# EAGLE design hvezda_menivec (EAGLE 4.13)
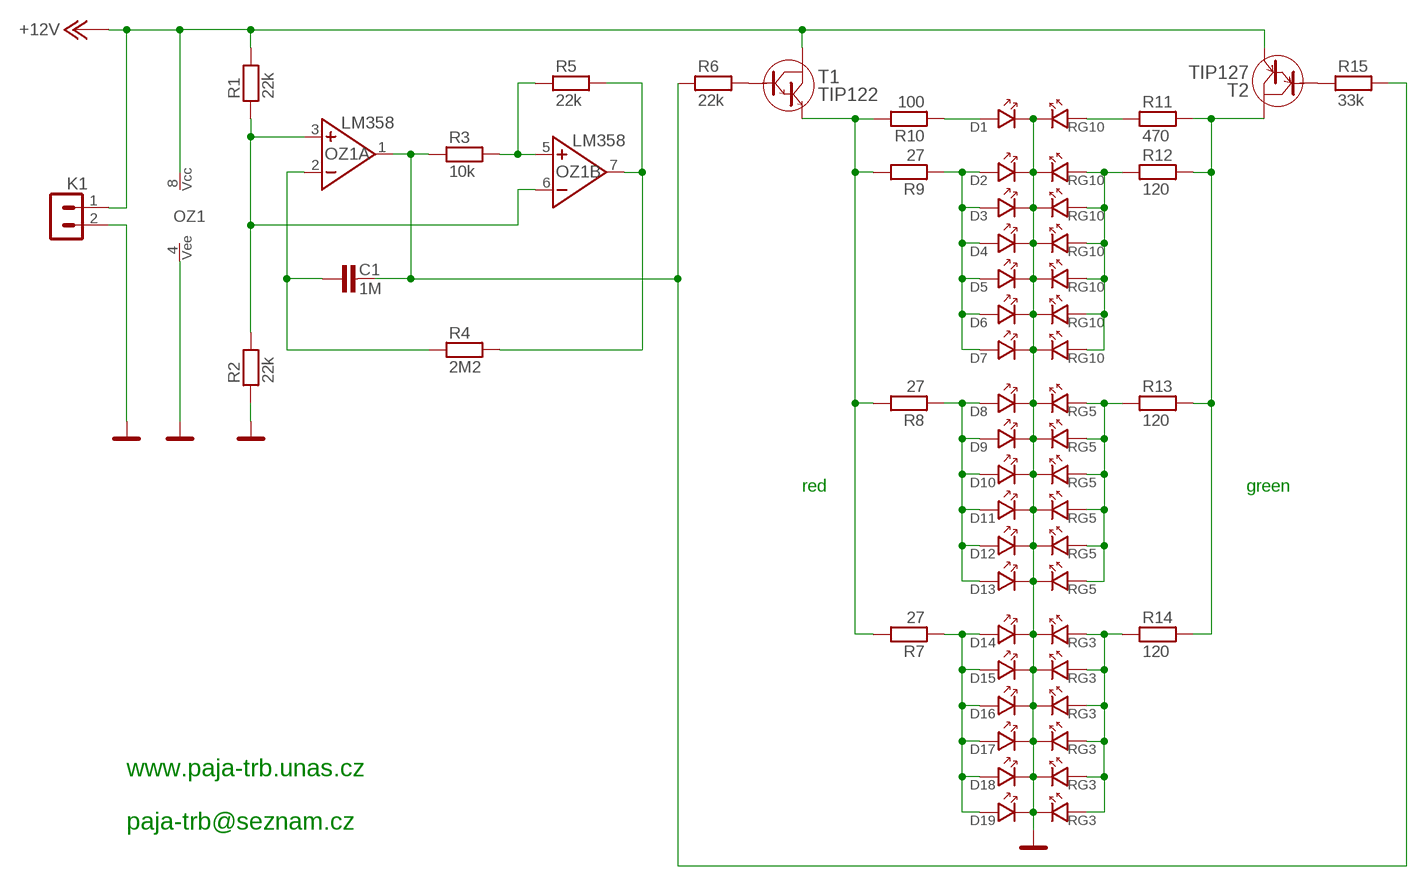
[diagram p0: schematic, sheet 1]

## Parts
C1  1M  1M-K/63V  [RM5_5,0]
D1  RG10  LED_DUO_10  [LED_10-DUO]
D2  RG10  LED_DUO_10  [LED_10-DUO]
D3  RG10  LED_DUO_10  [LED_10-DUO]
D4  RG10  LED_DUO_10  [LED_10-DUO]
D5  RG10  LED_DUO_10  [LED_10-DUO]
D6  RG10  LED_DUO_10  [LED_10-DUO]
D7  RG10  LED_DUO_10  [LED_10-DUO]
D8  RG5  LED_DUO_5  [LED_5-DUO]
D9  RG5  LED_DUO_5  [LED_5-DUO]
D10  RG5  LED_DUO_5  [LED_5-DUO]
D11  RG5  LED_DUO_5  [LED_5-DUO]
D12  RG5  LED_DUO_5  [LED_5-DUO]
D13  RG5  LED_DUO_5  [LED_5-DUO]
D14  RG3  LED_DUO_3  [LED_3-DUO]
D15  RG3  LED_DUO_3  [LED_3-DUO]
D16  RG3  LED_DUO_3  [LED_3-DUO]
D17  RG3  LED_DUO_3  [LED_3-DUO]
D18  RG3  LED_DUO_3  [LED_3-DUO]
D19  RG3  LED_DUO_3  [LED_3-DUO]
K1  PSH02-02W  [PSH02-02W]
OZ1  LM358  [DIL8]
R1  22k  R_SMD_1206  [1206]
R2  22k  R_SMD_1206  [1206]
R3  10k  R_SMD_1206  [1206]
R4  2M2  R_SMD_1206  [1206]
R5  22k  R_SMD_1206  [1206]
R6  22k  R_SMD_1206  [1206]
R7  27  R_SMD_1206  [1206]
R8  27  R_SMD_1206  [1206]
R9  27  R_SMD_1206  [1206]
R10  100  R_SMD_1206  [1206]
R11  470  R_SMD_1206  [1206]
R12  120  R_STOJ  [R-STOJ]
R13  120  R_STOJ  [R-STOJ]
R14  120  R_STOJ  [R-STOJ]
R15  33k  R_SMD_1206  [1206]
T1  TIP122  TIP122_STOJ  [TO-220S]
T2  TIP127  TIP127_STOJ  [TO-220S]

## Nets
+12V: K1.1 OZ1.8(NS:VCC) R1.2 T1.2(C) T2.3(E)
G3: D14.A2 D15.A2 D16.A2 D17.A2 D18.A2 D19.A2 R14.1
G5: D8.A2 D9.A2 D10.A2 D11.A2 D12.A2 D13.A2 R13.1
G8: D2.A2 D3.A2 D4.A2 D5.A2 D6.A2 D7.A2 R12.1
G10: D1.A2 R11.1
GND: D1.K D2.K D3.K D4.K D5.K D6.K D7.K D8.K D9.K D10.K D11.K D12.K D13.K D14.K D15.K D16.K D17.K D18.K D19.K K1.2 OZ1.4(NS:VEE) R2.1
N$1: OZ1.5(B:NEIN+) R3.2 R5.1
N$2: C1.2 OZ1.1(A:VYSTUP) R3.1 R6.1 R15.2
N$3: OZ1.3(A:NEIN+) OZ1.6(B:IN-) R1.1 R2.2
N$4: C1.1 OZ1.2(A:IN-) R4.1
N$6: OZ1.7(B:VYSTUP) R4.2 R5.2
N$8: R6.2 T1.1(B)
N$9: R7.2 R8.2 R9.2 R10.2 T1.3(E)
N$10: R15.1 T2.1(B)
N$11: R11.2 R12.2 R13.2 R14.2 T2.2(C)
R3: D14.A1 D15.A1 D16.A1 D17.A1 D18.A1 D19.A1 R7.1
R5: D8.A1 D9.A1 D10.A1 D11.A1 D12.A1 D13.A1 R8.1
R8: D2.A1 D3.A1 D4.A1 D5.A1 D6.A1 D7.A1 R9.1
R10: D1.A1 R10.1

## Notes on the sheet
- red | green
- www.paja-trb.unas.cz
- paja-trb@seznam.cz

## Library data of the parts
C1 = #PaJa_C-folie:1M-K/63V
D1-D19 = #PaJa_19:LED_DUO: LED dioda - 5mm prumer - dvoubarevna - 3 vyvody
K1 = #PaJa_19:PSH02-02: Konektory se zamkem - vidlice - 2pin
OZ1 = #PaJa_19:LM358: OZ - 2x - nizkoprikonovy
R1-R15 = #PaJa_19:R: Rezistor
T1 = #PaJa_19:TIP122
T2 = #PaJa_19:TIP127

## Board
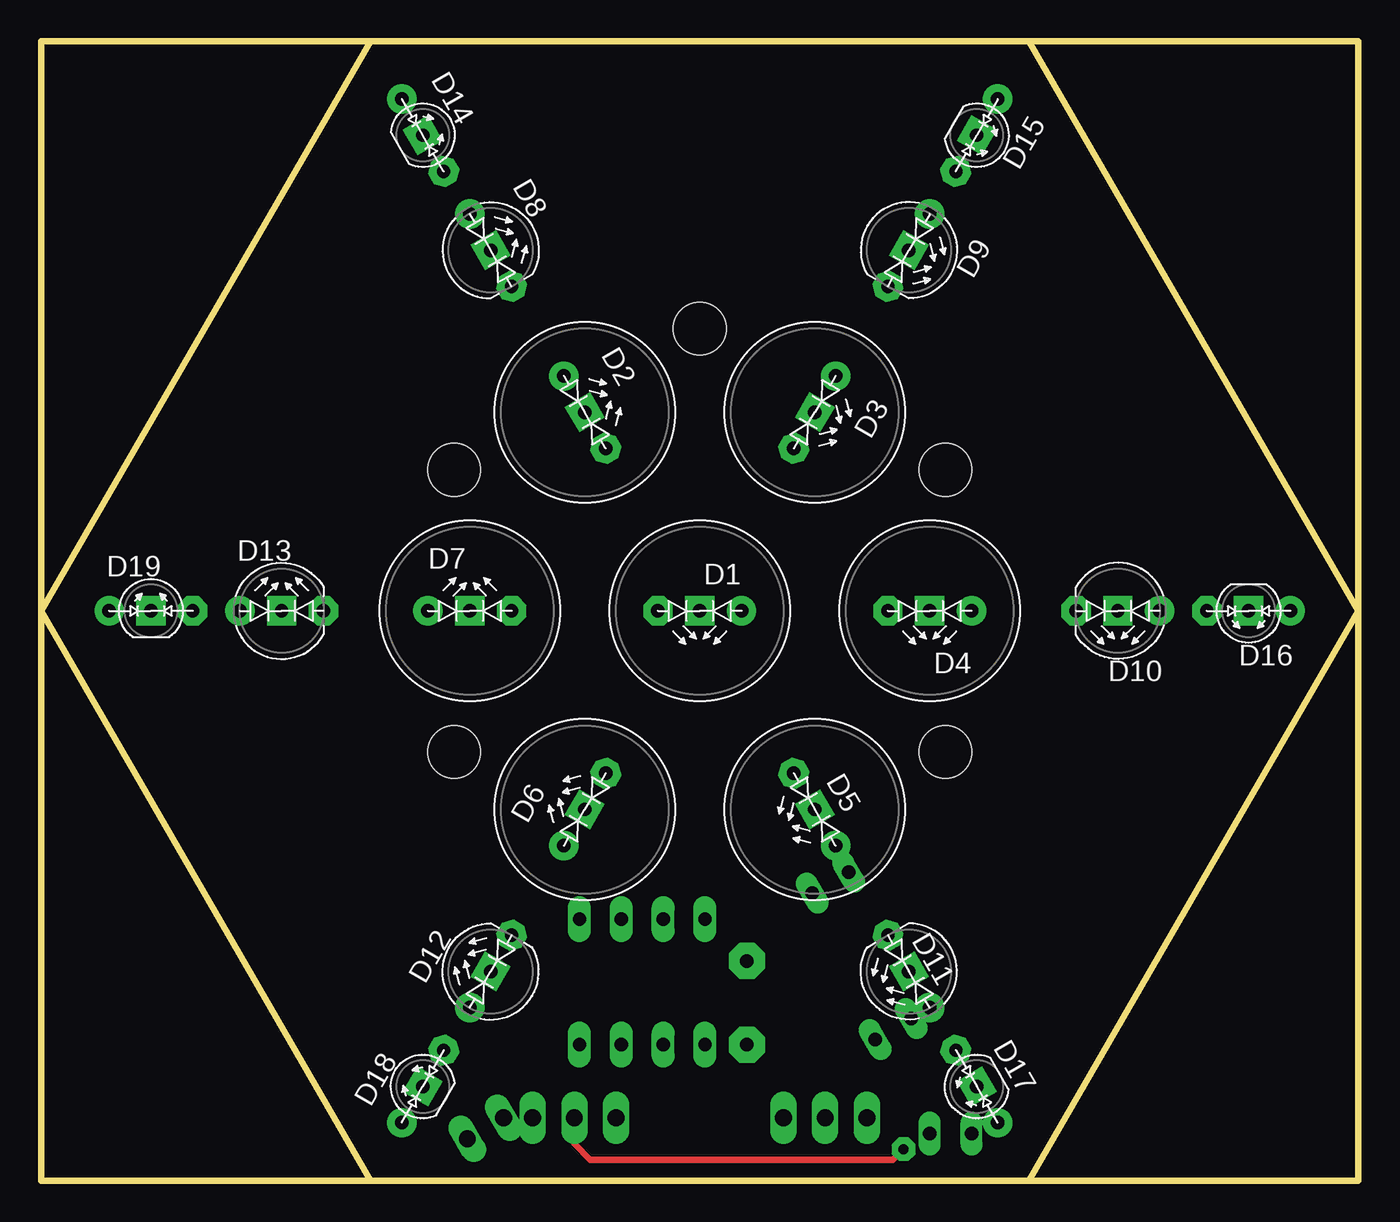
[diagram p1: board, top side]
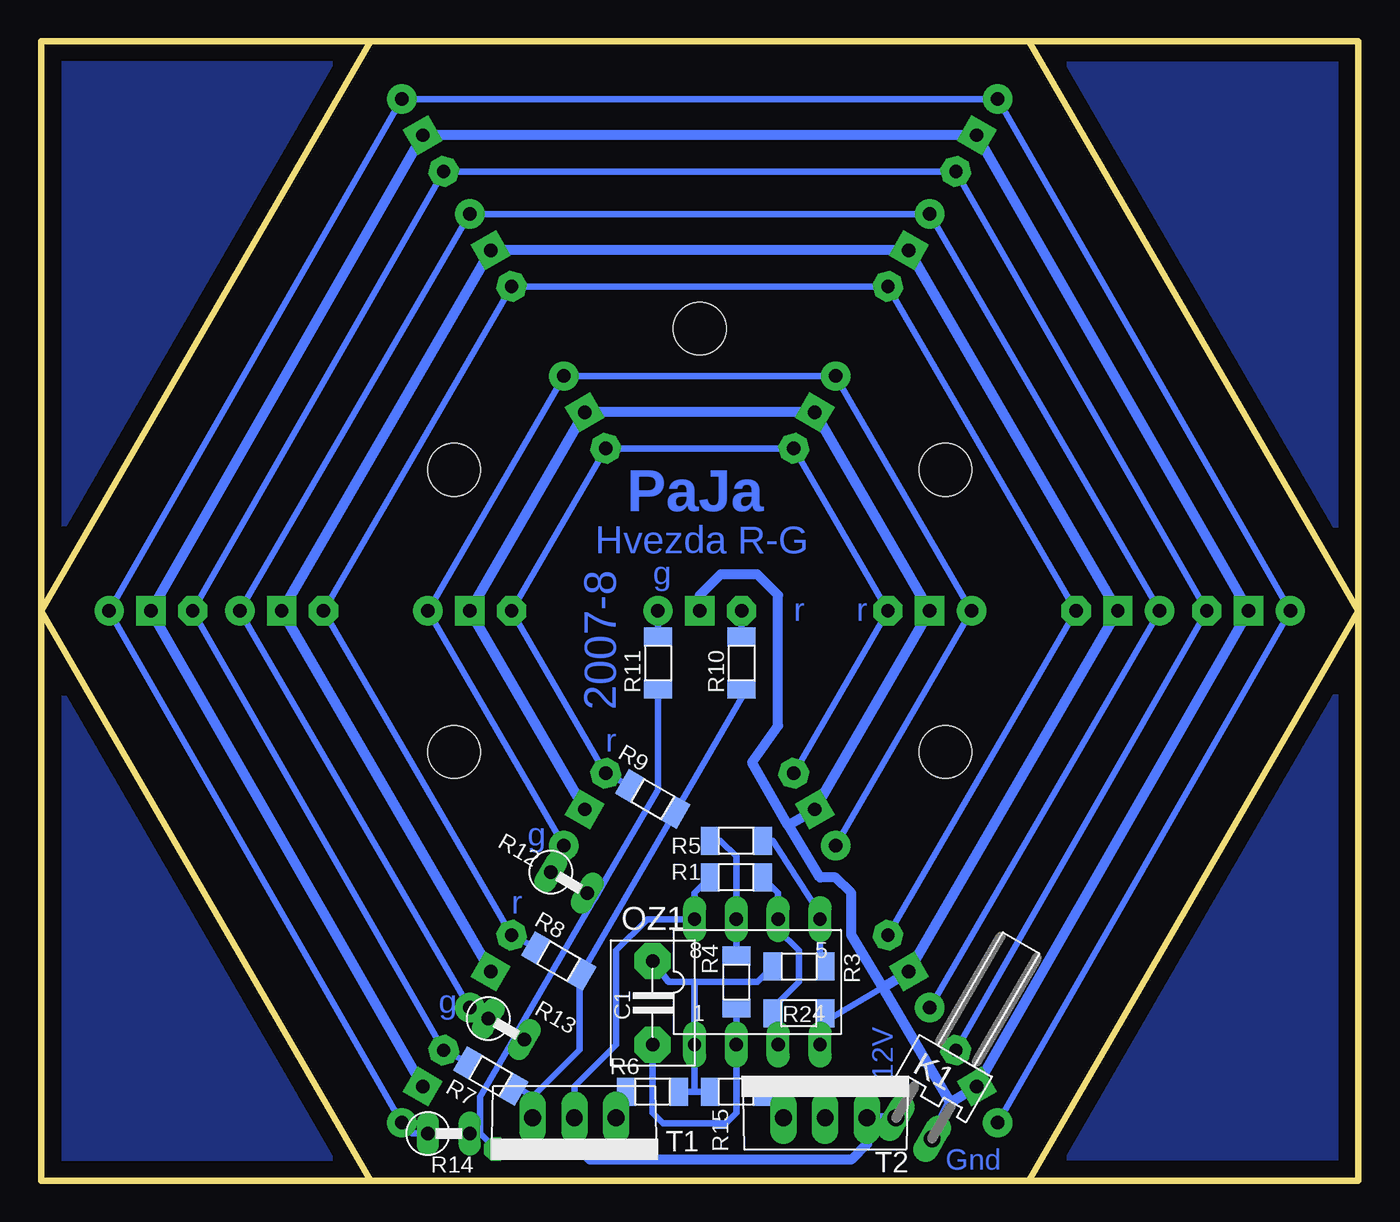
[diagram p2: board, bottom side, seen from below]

Size 80.01 x 69.22 mm. Coordinates in mm from the lower left corner, seen from the top.
Outline: 60.01,0 20,0
Outline: 20,0 0,34.61
Outline: 0,34.61 20,69.22
Outline: 80.01,34.61 60.01,69.22
Outline: 60.01,0 80.01,34.61
Outline: 20,69.22 0,69.22 0,34.61
Outline: 0,34.61 0,0 20,0
Outline: 60.01,69.22 80.01,69.22 80.01,34.61
Outline: 80.01,34.61 80.01,0 60.01,0
Outline: 60.01,69.22 20,69.22
Copper layers (1*16): Top 0.035mm / dielectric 1.5mm / Bottom 0.035mm
Design rules "default": minimum track width 10mil, minimum drill 24mil, track to track 8mil, track to pad 8mil, pad to pad 8mil, via to via 8mil, smd to smd 8mil, copper to edge 40mil, drill to drill 8mil, minimum pad ring 10mil, minimum via ring 8mil, stop-mask expansion 4mil, vias tented up to drill 0mil, thermal gap 10mil
Holes 3.2 mm at 25.08,26.04 54.93,43.18 25.08,43.18 54.93,26.04 40.01,51.75

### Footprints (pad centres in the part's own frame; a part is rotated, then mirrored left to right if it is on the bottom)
RM5_5,0 = drill 0.813 pad 2.184 octagon: 1 -2.54,0; 2 2.54,0
LED_10-DUO = drill 0.813 pad 1.778 octagon: A1 2.54,0 | drill 0.813 pad 1.778 round: A2 -2.54,0 | drill 0.813 pad 1.778 square: K 0,0
LED_5-DUO = drill 0.813 pad 1.778 octagon: A1 2.54,0 | drill 0.813 pad 1.778 round: A2 -2.54,0 | drill 0.813 pad 1.778 square: K 0,0
LED_3-DUO = drill 0.813 pad 1.778 octagon: A1 2.54,0 | drill 0.813 pad 1.778 round: A2 -2.54,0 | drill 0.813 pad 1.778 square: K 0,0
PSH02-02W = drill 1.016 pad 1.422 long: 1 -1.27,0; 2 1.27,0
DIL8 = drill 0.813 pad 1.4 long: 1 -3.81,-3.81; 2 -1.27,-3.81; 3 1.27,-3.81; 4 3.81,-3.81; 5 3.81,3.81; 6 1.27,3.81; 7 -1.27,3.81; 8 -3.81,3.81
1206 = smd 1.143 x 1.702: 1 -1.587,0; 2 1.587,0
R-STOJ = drill 0.813 pad 1.27 long: 1 -1.27,0; 2 1.27,0
TO-220S = drill 1.016 pad 1.6 long: 1 -2.54,0; 2 0,0; 3 2.54,0

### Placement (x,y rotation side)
C1  42.86,10.79 90 bottom
D1  40.01,34.61 180 top
D2  33.02,46.67 300 top
D3  46.99,46.67 240 top
D4  53.98,34.61 180 top
D5  46.99,22.54 120 top
D6  33.02,22.54 60 top
D7  26.04,34.61 0 top
D8  27.3,56.52 300 top
D9  52.7,56.52 240 top
D10  65.41,34.61 180 top
D11  52.7,12.7 120 top
D12  27.3,12.7 60 top
D13  14.61,34.61 0 top
D14  23.18,63.5 300 top
D15  56.83,63.5 240 top
D16  73.34,34.61 180 top
D17  56.83,5.71 120 top
D18  23.18,5.71 60 top
D19  6.67,34.61 0 top
K1  26.99,3.17 330 bottom
OZ1  36.51,12.06 0 bottom
R1  37.78,18.41 180 bottom
R2  33.97,10.16 180 bottom
R3  33.97,13.02 0 bottom
R4  37.78,12.06 90 bottom
R5  37.78,20.64 180 bottom
R6  42.86,5.4 180 bottom
R7  52.7,6.35 330 bottom
R8  48.58,13.34 330 bottom
R9  42.86,23.18 330 bottom
R10  37.47,31.43 270 bottom
R11  42.55,31.43 270 bottom
R12  47.94,18.1 330 bottom
R13  51.75,9.21 330 bottom
R14  55.24,2.86 0 bottom
R15  37.78,5.4 180 bottom
T1  47.62,3.81 180 bottom
T2  32.38,3.81 0 bottom

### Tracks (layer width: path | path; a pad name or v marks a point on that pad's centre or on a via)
+12V
  Bottom 0.406: R1.2 40.32,17.46 OZ1.8 43.18,15.88 45.09,13.97 45.09,8.26 47.62,5.71 T1.2
  Bottom 0.61: T1.2 47.62,2.22 46.67,1.27 30.8,1.27 29.84,2.22 T2.3 K1.1
G3
  Bottom 0.406: D18.A2 D19.A2 D14.A2 58.08,65.7 58.1,65.72 D15.A2 D16.A2 D17.A2 57.47,2.86 R14.1
G5
  Bottom 0.406: D12.A2 D13.A2 D8.A2 53.95,58.72 53.98,58.74 D9.A2 D10.A2 D11.A2 53.98,10.48 R13.1
G8
  Bottom 0.406: D3.A2 D2.A2 D7.A2 D6.A2 | D3.A2 48.26,48.9 | D3.A2 D4.A2 D5.A2 48.26,20.32 R12.1
G10
  Bottom 0.406: D1.A2 R11.1
GND
  Bottom 0.406: 33.09,22.44 D6.K | OZ1.4 32.7,10.16 R2.1 32.07,9.84 28.89,11.75
  Bottom 0.61: D5.K D4.K D3.K D2.K D7.K D6.K | D11.K D10.K D9.K D8.K D13.K D12.K 28.89,11.75 | D17.K D16.K D15.K D14.K D19.K D18.K 24.77,4.76 | 34.61,21.59 34.64,21.57 36.83,25.4 35.24,27.62 35.24,35.56 36.51,36.83 38.73,36.83 40.01,35.56 D1.K | 28.89,11.75 30.8,14.92 30.8,17.46 31.75,18.41 32.7,18.41 34.61,21.59 | 34.61,21.59 33.09,22.44 | K1.2 24.77,4.76 | 24.77,4.76 28.89,11.75
N$1
  Bottom 0.406: R3.2 32.7,13.02 OZ1.5 32.7,16.19 35.56,20.64 R5.1
N$2
  Bottom 0.406: 40.32,12.06 36.51,12.06 R3.1 | 40.32,12.06 OZ1.1 40.32,5.4 | 40.32,12.06 41.91,12.06 C1.2 | R15.2 40.32,5.4 | 40.32,5.4 R6.1
N$3
  Bottom 0.406: R1.1 35.24,17.46 OZ1.6 35.24,15.24 33.97,13.97 33.97,12.06 35.24,10.79 35.24,10.16 | OZ1.3 35.24,10.16 | 35.24,10.16 R2.2
N$4
  Bottom 0.406: R4.1 OZ1.2 37.78,4.13 38.42,3.49 42.23,3.49 42.86,4.13 C1.1
N$5
  pour Bottom: 20,69.22 0,69.22 0,34.61
  pour Bottom: 60.01,0 80.01,0 80.01,34.61
  pour Bottom: 20,0 0,0 0,34.61
  pour Bottom: 60.01,69.22 80.01,69.22 80.01,34.61
N$6
  Bottom 0.406: R4.2 OZ1.7 37.78,19.68 38.73,20.64 R5.2
N$8
  Bottom 0.406: R6.2 45.09,4.76 T1.1
N$9
  Bottom 0.406: R10.2 37.47,29.53 37.38,29.48 R9.2 41.59,22.23 R8.2 47.31,12.44 47.31,7.94 50.16,5.08 | T1.3 50.16,5.08 | R7.2 51.17,5.71 50.16,5.08
N$10
  Bottom 0.406: R15.1 35.88,5.4 34.92,4.45 T2.1
N$11  (via drill 0.6 pad 1.42)
  Top 0.406: T2.2 32.38,2.22 33.34,1.27 51.75,1.27 v52.39,1.91
  Bottom 0.406: 45.45,18.76 51.17,8.92 51.12,8.89 | 45.45,18.76 42.52,23.8 42.55,23.81 R11.2 | 51.12,8.89 R13.2 | R12.2 46.35,17.14 45.45,18.76 | 51.12,8.89 53.34,5.08 53.34,2.86 | 53.34,2.86 R14.2 | v52.39,1.91 53.34,2.86
R3
  Bottom 0.406: 55.56,61.28 D15.A1 | 55.56,61.28 55.54,61.3 D14.A1 D19.A1 D18.A1 | 55.56,61.28 D16.A1 D17.A1 55.56,7.94 R7.1
R5
  Bottom 0.406: D12.A1 D13.A1 D8.A1 51.41,54.31 51.44,54.29 D9.A1 D10.A1 D11.A1 51.44,14.92 R8.1
R8
  Bottom 0.406: D6.A1 D7.A1 D2.A1 D3.A1 45.72,44.45 D4.A1 D5.A1 45.72,24.77 R9.1
R10
  Bottom 0.406: D1.A1 R10.1

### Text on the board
Bottom: PaJa | Hvezda R-G | g | r | r | 2007-8 | r | g | r | g | +12V | Gnd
